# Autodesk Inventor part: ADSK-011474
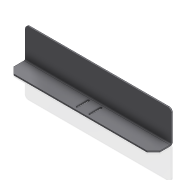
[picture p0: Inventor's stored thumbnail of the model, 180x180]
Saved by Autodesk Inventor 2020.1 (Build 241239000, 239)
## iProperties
Created: 2000-01
Part Number: ADSK-011474
Material: 1.0312 DC05
Description: FSHTPH,SS,CX,01,050,030,230,090,
Document SubType Name: Tôlerie
Designer: cmcgourin
Density: 1 g/cm^3
Sheet Metal Rule: Stahlblech 1.0312 - DC05 -   5.0 mm
Appearance: Metal-Steel(Polish)
Mass: 562.391 g
Surface Area: 2336.58 cm^2
Volume: 562.391 cm^3
Flat Pattern Width: 19.451 cm
Flat Pattern Length: 58.42 cm
Flat Pattern Area: 1136.33 cm^2
Sheet Metal Width: 194,510 mm
Sheet Metal Length: 584,200 mm
Sheet Metal Area: 113632,586 mm^2
Control State: 0
Checked Out: False
Master: False
Shininess: 60.0
Length Units: 11269
Angle Units: 11279
Time Units: 11290
Mass Units: 11283
Length Display Precision: 3
Angle Display Precision: 2
Compacted: True
Cutlength: 177 SI (7.67 X 23.00)
Material_Number: A101293
G_L: 584,2x194,5 mm
Thickness: 5,000 mm
Dimensions: 76,2x127x584,2 mm
Mass: 0,562 kg
Semi finished: Stahlblech 1.0312 - DC05 -   5.0 mm
Density: 8.03
Volumn: 544.9098424755208
Area: 2352.85296820069
PropertySet Name: Model Information
Author: cmcgourin
Revision Number: -
Title: FSHTPH,SS,CX,01,050,030,230,090,
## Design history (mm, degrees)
node "Extrusion1" dims "d2" = 584.2, "d3" = 0
node "Extrusion2" dims "d6" = 711.2, "d7" = 0
node "Fillet3" dims "d10" = 12.7
node "Fillet4" dims "d11" = 12.7
node "Chamfer1" dims "d12" = 25.4, "d13" = 25.4, "d39" = 45 deg
node "Chamfer2" dims "d14" = 25.4, "d15" = 25.4, "d40" = 45 deg
node "End_mill_straight1"
node "End_mill_straight2"
node "Bend1" dims "d34" = 5 (= BendRadius), "d36" = 5 (= BendReliefWidth), "d37" = 2.5 (= BendReliefDepth), "d38" = 10 (= MinimumRemnant), "d41" = 5 (= Thickness), "SeamGap" = 0.00508, "MinimumRemnant" = 10 (= 2 x Thickness), "BendReliefWidth" = 5 (= Thickness)
workplane "Work Plane1"
node "Solide1"
node "Corps solides"
node "Corps surfaciques"
sketch "Sketch1"
  geometry: L1 (0, 0)-(76.2, 0); L2 (76.2, 0)-(76.2, 127); L3 (76.2, 127)-(0, 127); L4 (0, 127)-(0, 0); 1 further point
  constraints: 8 end point, 2 parallel, 1 coincident, 1 horizontal, 1 perpendicular
  dimensions: "d0" = 127 distance of L3.end L1.start; "d1" = 76.2 distance of L1.start L1.end
sketch "Sketch2"
  geometry: L1 (0, 0)-(76.2, 0) reference; L2 (76.2, 0)-(76.2, 127) reference; L3 (0, 127)-(71.2, 127); L4 (71.2, 127)-(71.2, 5); L5 (71.2, 5)-(0, 5); L6 (0, 5)-(0, 127)
  constraints: 8 end point, 2 parallel, 1 horizontal, 1 perpendicular
  dimensions: "d4" = 5 distance between parallel lines of L2 L4 (= Thickness); "d5" = 5 distance between parallel lines of L1 L5 (= Thickness)
sketch "Sketch3"
  geometry: L1 (-243.413, -326.166)-(-243.413, -281.716); L2 (-250.557, -281.716)-(-250.557, -326.166); L3 (-246.985, -326.166)-(-246.985, -281.716); L4 (45.115, -338.866)-(-488.285, -338.866) reference; C1 r 1.842 at (46.703, -27.716) reference; C2 r 1.842 at (27.653, -27.716) reference; C3 r 1.842 at (27.653, -65.816) reference; C4 r 1.842 at (46.703, -65.816) reference; A1 r 3.572 centre (-246.985, -326.166) between (-250.557, -326.166) and (-243.413, -326.166); A2 r 3.572 centre (-246.985, -281.716) between (-243.413, -281.716) and (-250.557, -281.716); 2 further points; 1 other entity
  constraints: 6 end point, 4 point on circle, 4 tangent, 2 centre point, 1 parallel, 1 other
  dimensions: "d16" = 3.57187 radius of A2 (derived); "d28" = 266.7 dimension on L3; "d29" = 12.7 distance from line of L3.start L4; "d30" = 57.15 distance from line of L3.end L4
sketch "Sketch4"
  geometry: L1 (-192.61, -326.033)-(-192.61, -281.583); L2 (-199.754, -281.583)-(-199.754, -326.033); L3 (-196.182, -326.033)-(-196.182, -281.583); L4 (45.118, -338.733)-(-488.282, -338.733) reference; C1 r 1.842 at (27.655, -65.683) reference; C2 r 1.842 at (46.705, -65.683) reference; A1 r 3.572 centre (-196.182, -326.033) between (-199.754, -326.033) and (-192.61, -326.033); A2 r 3.572 centre (-196.182, -281.583) between (-192.61, -281.583) and (-199.754, -281.583); 2 further points; 1 other entity
  constraints: 6 end point, 4 point on circle, 4 tangent, 2 centre point, 1 parallel, 1 other
  dimensions: "d23" = 3.57187 radius of A2 (derived); "d31" = 12.7 distance from line of L3.start L4; "d32" = 57.15 distance from line of L4 L3.end; "d33" = 317.5 dimension on L3
feature "Definition1"
other parameters: "Thickness" = 5 (derived), "BendRadius" = 5 (= Thickness), "BendReliefDepth" = 2.5 (= 0.5 x Thickness), "d35" = -292.1, "TransitionRadius" = 5 (= BendRadius), "TailleRayonJacobi" = 5 (= BendRadius), "TailleJeu" = 5 (= Thickness), "BendRadius" = 5, "BendReliefDepth" = 2.5, "BendReliefWidth" = 5, "TailleJeu" = 5, "TailleRayonJacobi" = 5, "Thickness" = 5, "TransitionRadius" = 5
